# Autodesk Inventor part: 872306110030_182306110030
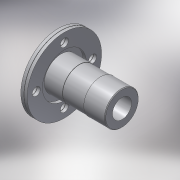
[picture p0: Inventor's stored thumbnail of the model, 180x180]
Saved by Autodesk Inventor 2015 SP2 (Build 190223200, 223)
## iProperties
Created: 2017-02
Part Number: 872306110030_182306110030
Material: PVC-Piping
Description: PLASSON FLANGE ADAPTOR WITH METAL FLANGE 110-3"
Document SubType Name: Modeling
Designer: KIM
Mass: 92.6774 g
Surface Area: 199.44 cm^2
Volume: 66.1981 cm^3
Density: 1.4 g/cm^3
Appearance: Smooth - White
Author: Кирилл
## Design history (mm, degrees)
derived "872306.ipt"
feature "Solid1::872306.ipt"
tag "TaggingFeature1"
body "Solid1"
other parameters: "d73" = 21, "d74" = 90 deg, "d75" = 0.3, "d77" = 18, "d80" = 0, "d82" = 360 deg, "d96" = 0.3, "d99" = 360 deg, "d104" = 2.2, "d107" = 132, "d108" = 5.25, "d116" = 107.8, "d120" = 5.5, "S_" = 18
